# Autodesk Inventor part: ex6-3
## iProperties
Author: Administrator
Revision Number: A
Created: 2001-10
Part Number: ex6-3
Description: WHEEL
Document SubType Name: Modeling
Designer: E. MOSS
Control State: 0
Master: False
Checked Out: False
PropertySet Name: Design Tracking Control
Shininess: 20.0
Angle Display Precision: 2
Document Length Units: 11272
Document Angle Units: 11286
Document Time Units: 11279
Document Mass Units: 11290
Document Length Units Precision: 3
Document Angle Units Precision: 2
Compacted: False
PropertySet Name: _Private Model Information
Density: 0.0
Volumn: 0.0
Area: 0.0
PropertySet Name: Model Information
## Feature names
1. Revolution1
2. Tire [Revolution]
3. Extrusion1
4. Circular Pattern1
